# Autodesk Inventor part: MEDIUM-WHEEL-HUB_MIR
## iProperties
Created: 2007-08
Part Number: MEDIUM-WHEEL-HUB_MIR
Material: ABS Plastic
Document SubType Name: Modeling
Mass: 42.8255 g
Surface Area: 324.402 cm^2
Volume: 40.4014 cm^3
Density: 1.06 g/cm^3
